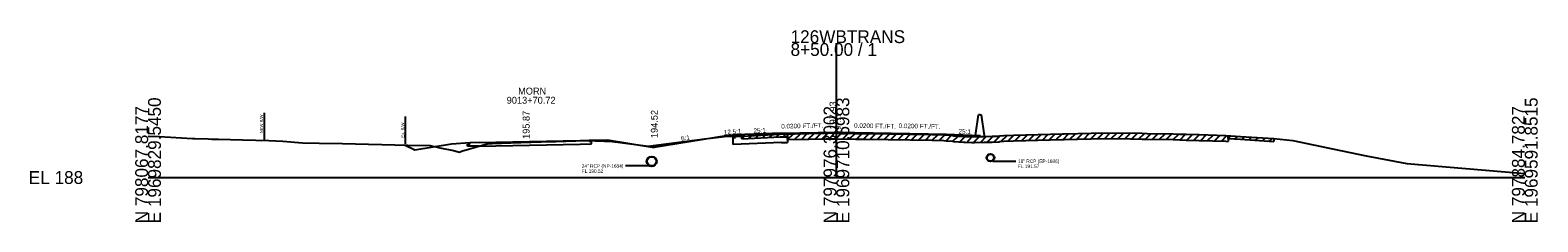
# Model space of a CAD drawing. Extents: x -6494 to 1970605, y -10 to 798140.
# Drawn here: x -25.7 to 302.8, y 990.3 to 1032.2 of the extents above; entities that cross this region are included whole.
import ezdxf

# ---------------------------------------------------------------- set-up
doc = ezdxf.new("R2010")
doc.units = 0
for name, color, linetype in [('RD_GPK_XS_Cell', 7, 'Continuous'), ('RD_XS_Base', 7, 'Continuous'), ('RD_XS_EarthShd', 7, 'Continuous'), ('RD_XS_ExGround', 7, 'Continuous'), ('RD_XS_ExPaveRet', 7, 'Continuous'), ('RD_XS_ExRW', 7, 'Continuous'), ('RD_XS_MedBWall', 7, 'Continuous'), ('RD_XS_Misc_Line', 7, 'Continuous'), ('RD_XS_NewRW', 7, 'Continuous'), ('RD_XS_Pave', 7, 'Continuous'), ('RD_XS_PaveOvlay', 7, 'Continuous'), ('RD_XS_PaveShd', 7, 'Continuous'), ('RD_XS_Pipe', 7, 'Continuous'), ('RD_XS_TieSlope', 7, 'Continuous'), ('RD_XS_TX_Elev_EX', 7, 'Continuous'), ('RD_XS_TX_Elev_PR', 7, 'Continuous'), ('RD_XS_TX_Misc', 7, 'Continuous'), ('RD_XS_TX_Profile', 7, 'Continuous'), ('RD_XS_TX_ShdSlope', 7, 'Continuous'), ('RD_XS_TX_Slope', 7, 'Continuous'), ('RD_XS_TX_Station', 7, 'Continuous')]:
    doc.layers.add(name, color=color, linetype=linetype)

msp = doc.modelspace()

# ---------------------------------------------------------------- linework, layer by layer
at = {"layer": 'RD_GPK_XS_Cell'}
for p, q in [((150, 1000), (150, 1029.35)), ((0, 1000), (150, 1000)), ((150, 1000), (300, 1000))]:
    msp.add_line(p, q, dxfattribs=at)
at = {"layer": 'RD_XS_Base'}
for p, q in [((127.5, 1008.71), (128, 1008.73)), ((127.5, 1007.23), (127.5, 1008.71)), ((128, 1008.73), (128, 1009.29)), ((69.64, 1007.29), (70.14, 1007.3)), ((69.64, 1006.81), (69.64, 1007.29)), ((72.14, 1006.86), (69.64, 1006.81)), ((70.14, 1007.3), (70.14, 1007.6)), ((94.14, 1007.31), (96.64, 1007.36)), ((96.14, 1007.83), (96.14, 1008.13)), ((96.64, 1007.84), (96.14, 1007.83)), ((96.64, 1007.36), (96.64, 1007.84)), ((138, 1007.65), (127.5, 1007.23)), ((138, 1007.65), (139.37, 1007.68))]:
    msp.add_line(p, q, dxfattribs=at)
at = {"layer": 'RD_XS_EarthShd'}
for p, q in [((128, 1009.29), (126, 1009.13)), ((70.14, 1007.6), (66.13, 1007.28)), ((96.14, 1008.13), (100.14, 1008.21))]:
    msp.add_line(p, q, dxfattribs=at)
at = {"layer": 'RD_XS_ExGround'}
msp.add_lwpolyline([(0, 1009), (2.52, 1008.93), (9.69, 1008.54), (10.19, 1008.53), (13.08, 1008.41), (13.87, 1008.39), (15.37, 1008.35), (20.59, 1008.25), (26.33, 1008.08), (29.35, 1007.9), (33.63, 1007.59), (37.29, 1007.49), (42.4, 1007.42), (56.62, 1007.07), (61.49, 1007.02), (63.6, 1006.51), (66.52, 1005.88), (67.89, 1005.52), (68.28, 1005.74), (73.89, 1007.36), (74.97, 1007.41), (79.08, 1007.56), (85.68, 1007.81), (88.82, 1007.88), (95.37, 1008.05), (99.44, 1007.97), (100.48, 1007.95), (102.33, 1007.71), (109, 1006.85), (121.29, 1008.46), (126.25, 1009.05), (127.43, 1009.06), (129.37, 1009.04), (137.76, 1009.5), (143.96, 1009.59), (147.74, 1009.68), (149.38, 1009.72), (150.2, 1009.71), (154.17, 1009.64), (156.42, 1009.62), (161.26, 1009.54), (170.76, 1009.37), (173.37, 1009.31), (173.9, 1009.29), (175.33, 1009.2), (175.61, 1009.1), (177.78, 1008.96), (178.08, 1008.94), (179.51, 1008.92), (180.09, 1008.92), (182.21, 1008.94), (183.91, 1009), (185.36, 1009.05), (185.6, 1009.13), (186.51, 1009.17), (188.58, 1009.26), (199.26, 1009.56), (199.59, 1009.57), (205.5, 1009.66), (211.52, 1009.78), (216.65, 1009.65), (217.74, 1009.63), (223.39, 1009.54), (224.8, 1009.49), (226.21, 1009.44), (229.05, 1009.36), (234.88, 1009.16), (238.06, 1008.97), (245.34, 1008.5), (248.04, 1008.22), (249.42, 1008.07), (258.46, 1006.16), (265.4, 1004.74), (274.3, 1003.04), (287.15, 1002), (300, 1000.88)], dxfattribs=at)
at = {"layer": 'RD_XS_ExPaveRet'}
for p, q in [((129.37, 1008.41), (129.37, 1009.04)), ((129.37, 1008.41), (137.76, 1008.87)), ((137.76, 1008.87), (139.37, 1008.9)), ((139.37, 1008.27), (139.37, 1009.52)), ((139.37, 1009.52), (139.37, 1008.9)), ((235.34, 1009.13), (235.34, 1007.88)), ((235.34, 1008.51), (235.34, 1009.13)), ((139.37, 1008.27), (143.96, 1008.34)), ((143.96, 1008.34), (147.74, 1008.43)), ((147.74, 1008.43), (149.38, 1008.47)), ((149.38, 1008.47), (150.2, 1008.46)), ((150.2, 1008.46), (154.17, 1008.39)), ((154.17, 1008.39), (156.42, 1008.37)), ((156.42, 1008.37), (161.26, 1008.29)), ((161.26, 1008.29), (170.76, 1008.12)), ((170.76, 1008.12), (173.37, 1008.06)), ((173.37, 1008.06), (173.9, 1008.04)), ((173.9, 1008.04), (175.33, 1007.95)), ((175.33, 1007.95), (175.61, 1007.85)), ((175.61, 1007.85), (177.78, 1007.71)), ((177.78, 1007.71), (178.08, 1007.69)), ((178.08, 1007.69), (179.51, 1007.67)), ((179.51, 1007.67), (180.09, 1007.67)), ((180.09, 1007.67), (182.21, 1007.69)), ((182.21, 1007.69), (183.91, 1007.75)), ((183.91, 1007.75), (185.36, 1007.8)), ((185.36, 1007.8), (185.6, 1007.88)), ((185.6, 1007.88), (186.51, 1007.92)), ((186.51, 1007.92), (188.58, 1008.01)), ((188.58, 1008.01), (199.26, 1008.31)), ((199.26, 1008.31), (199.59, 1008.32)), ((199.59, 1008.32), (205.5, 1008.41)), ((205.5, 1008.41), (211.52, 1008.53)), ((211.52, 1008.53), (216.65, 1008.4)), ((216.65, 1008.4), (217.74, 1008.38)), ((217.74, 1008.38), (223.39, 1008.29)), ((223.39, 1008.29), (224.8, 1008.24)), ((224.8, 1008.24), (226.21, 1008.19)), ((226.21, 1008.19), (229.05, 1008.11)), ((229.05, 1008.11), (234.88, 1007.91)), ((234.88, 1007.91), (235.34, 1007.88)), ((235.34, 1008.51), (238.06, 1008.34)), ((238.06, 1008.34), (245.34, 1007.87)), ((245.34, 1008.5), (245.34, 1007.87))]:
    msp.add_line(p, q, dxfattribs=at)
at = {"layer": 'RD_XS_ExRW'}
msp.add_line((56.06, 1013.33), (56.06, 1007.33), dxfattribs=at)
at = {"layer": 'RD_XS_MedBWall'}
for p, q in [((180.29, 1009.18), (180.96, 1013.66)), ((181.29, 1013.66), (180.96, 1013.66)), ((181.29, 1013.66), (181.63, 1013.66)), ((182.29, 1009.18), (181.63, 1013.66))]:
    msp.add_line(p, q, dxfattribs=at)
at = {"layer": 'RD_XS_Misc_Line'}
for p, q in [((129.37, 1008.41), (130.04, 1009.08)), ((130.87, 1008.5), (131.54, 1009.16)), ((132.37, 1008.58), (133.04, 1009.24)), ((133.87, 1008.66), (134.54, 1009.32)), ((135.37, 1008.74), (136.04, 1009.4)), ((136.87, 1008.82), (137.54, 1009.48)), ((138.37, 1008.88), (139.01, 1009.52)), ((139.37, 1008.27), (140.64, 1009.54)), ((140.87, 1008.29), (142.14, 1009.56)), ((142.37, 1008.32), (143.64, 1009.58)), ((143.87, 1008.34), (145.15, 1009.62)), ((145.37, 1008.37), (146.66, 1009.65)), ((146.88, 1008.41), (148.16, 1009.69)), ((148.38, 1008.45), (149.65, 1009.72)), ((149.88, 1008.46), (151.11, 1009.69)), ((151.38, 1008.44), (152.61, 1009.67)), ((152.88, 1008.41), (154.11, 1009.64)), ((154.38, 1008.39), (155.61, 1009.63)), ((155.88, 1008.37), (157.11, 1009.61)), ((157.38, 1008.35), (158.61, 1009.58)), ((158.88, 1008.33), (160.11, 1009.56)), ((160.38, 1008.31), (161.61, 1009.54)), ((161.88, 1008.28), (163.1, 1009.51)), ((163.38, 1008.25), (164.6, 1009.48)), ((164.88, 1008.23), (166.1, 1009.45)), ((166.38, 1008.2), (167.6, 1009.43)), ((167.88, 1008.17), (169.1, 1009.4)), ((169.38, 1008.14), (170.6, 1009.37)), ((170.88, 1008.12), (172.1, 1009.34)), ((172.38, 1008.08), (173.59, 1009.3)), ((173.88, 1008.04), (175.05, 1009.21)), ((175.38, 1007.93), (176.49, 1009.04)), ((176.88, 1007.77), (178.05, 1008.94)), ((178.38, 1007.68), (179.61, 1008.92)), ((179.88, 1007.67), (181.14, 1008.93)), ((181.38, 1007.68), (182.65, 1008.96)), ((182.88, 1007.71), (184.17, 1009.01)), ((184.38, 1007.77), (185.75, 1009.14)), ((185.88, 1007.9), (187.18, 1009.2)), ((187.38, 1007.96), (188.68, 1009.26)), ((188.88, 1008.02), (190.16, 1009.3)), ((190.38, 1008.06), (191.66, 1009.34)), ((191.88, 1008.1), (193.16, 1009.39)), ((193.38, 1008.14), (194.66, 1009.43)), ((194.88, 1008.18), (196.16, 1009.47)), ((196.38, 1008.23), (197.66, 1009.51)), ((197.88, 1008.27), (199.16, 1009.55)), ((199.38, 1008.31), (200.65, 1009.58)), ((200.88, 1008.34), (202.14, 1009.6)), ((202.38, 1008.36), (203.64, 1009.63)), ((203.88, 1008.38), (205.14, 1009.65)), ((205.38, 1008.4), (206.65, 1009.68)), ((206.88, 1008.43), (208.15, 1009.71)), ((208.38, 1008.47), (209.65, 1009.74)), ((209.88, 1008.5), (211.15, 1009.77)), ((211.38, 1008.53), (212.6, 1009.75)), ((212.88, 1008.5), (214.09, 1009.71)), ((214.38, 1008.46), (215.59, 1009.67)), ((215.88, 1008.42), (217.1, 1009.64)), ((217.38, 1008.38), (218.61, 1009.62)), ((218.88, 1008.36), (220.11, 1009.59)), ((220.38, 1008.34), (221.61, 1009.57)), ((221.88, 1008.32), (223.11, 1009.55)), ((223.38, 1008.29), (224.58, 1009.5)), ((224.88, 1008.24), (226.08, 1009.45)), ((226.38, 1008.19), (227.59, 1009.4)), ((227.88, 1008.14), (229.09, 1009.36)), ((229.38, 1008.1), (230.59, 1009.31)), ((230.88, 1008.05), (232.09, 1009.26)), ((232.38, 1008), (233.59, 1009.21)), ((233.88, 1007.95), (235.08, 1009.15)), ((235.34, 1008.51), (235.93, 1009.1)), ((236.84, 1008.42), (237.43, 1009)), ((238.34, 1008.32), (238.93, 1008.91)), ((239.84, 1008.23), (240.43, 1008.81)), ((241.34, 1008.13), (241.93, 1008.72)), ((242.84, 1008.03), (243.43, 1008.62)), ((244.34, 1007.94), (244.93, 1008.52))]:
    msp.add_line(p, q, dxfattribs=at)
at = {"layer": 'RD_XS_NewRW'}
msp.add_line((25.29, 1014.11), (25.29, 1008.11), dxfattribs=at)
at = {"layer": 'RD_XS_Pave'}
for p, q in [((138, 1009.69), (150, 1009.93)), ((150, 1009.93), (174, 1009.45)), ((72.14, 1007.64), (83.14, 1007.87)), ((72.14, 1006.86), (83.14, 1007.09)), ((83.14, 1007.87), (94.14, 1008.09)), ((83.14, 1007.09), (94.14, 1007.31))]:
    msp.add_line(p, q, dxfattribs=at)
at = {"layer": 'RD_XS_PaveOvlay'}
for p, q in [((139.37, 1009.52), (143.96, 1009.59)), ((139.37, 1009.52), (139.37, 1007.68)), ((143.96, 1009.59), (147.74, 1009.68)), ((147.74, 1009.68), (149.38, 1009.72)), ((149.38, 1009.72), (150.2, 1009.71)), ((150.2, 1009.71), (154.17, 1009.64)), ((154.17, 1009.64), (156.42, 1009.62)), ((156.42, 1009.62), (161.26, 1009.54)), ((161.26, 1009.54), (170.76, 1009.37)), ((170.76, 1009.37), (173.37, 1009.31)), ((173.37, 1009.31), (173.9, 1009.29)), ((173.9, 1009.29), (175.33, 1009.2)), ((175.33, 1009.2), (175.61, 1009.1)), ((175.61, 1009.1), (177.78, 1008.96)), ((177.78, 1008.96), (178.08, 1008.94)), ((178.08, 1008.94), (179.51, 1008.92)), ((179.51, 1008.92), (180.09, 1008.92)), ((180.09, 1008.92), (181.29, 1008.93))]:
    msp.add_line(p, q, dxfattribs=at)
at = {"layer": 'RD_XS_PaveShd'}
for p, q in [((138, 1009.69), (128, 1009.29)), ((174, 1009.45), (181.29, 1009.16)), ((181.29, 1008.93), (181.29, 1009.16)), ((72.14, 1007.64), (70.14, 1007.6)), ((94.14, 1008.09), (96.14, 1008.13))]:
    msp.add_line(p, q, dxfattribs=at)
at = {"layer": 'RD_XS_Pipe'}
for p, q in [((109.07, 1002.52), (104.07, 1002.52)), ((184.06, 1003.57), (189.06, 1003.57))]:
    msp.add_line(p, q, dxfattribs=at)
for centre, radius in [((109.74, 1003.52), 1.1), ((109.74, 1003.52), 1), ((183.56, 1004.32), 0.85), ((183.56, 1004.32), 0.75)]:
    msp.add_circle(centre, radius, dxfattribs=at)
at = {"layer": 'RD_XS_TieSlope'}
for p, q in [((126, 1009.13), (110.31, 1006.52)), ((58.13, 1005.95), (55.85, 1007.09)), ((66.13, 1007.28), (58.13, 1005.95)), ((100.14, 1008.21), (110.31, 1006.52)), ((110.31, 1006.52), (110.31, 1007.02))]:
    msp.add_line(p, q, dxfattribs=at)

# ---------------------------------------------------------------- texts
at = {"layer": 'RD_GPK_XS_Cell'}
for s, p in [('126WBTRANS', (140, 1029.35)), ('8+50.00 / 1', (140, 1026.55)), ('EL 188', (-26, 998.6))]:
    msp.add_text(s, height=2.8, dxfattribs=at).set_placement(p)
for s, p in [('N 798067.8177', (0, 990)), ('E 1969829.5450', (2.8, 990)), ('N 797976.3002', (150, 990)), ('E 1969710.6983', (152.8, 990)), ('N 797884.7827', (300, 990)), ('E 1969591.8515', (302.8, 990))]:
    msp.add_text(s, height=2.8, rotation=90, dxfattribs=at).set_placement(p)
at = {"layer": 'RD_XS_ExRW'}
msp.add_text('Ex. R/W ', height=0.65, rotation=90, dxfattribs=at).set_placement((55.81, 1008.72))
at = {"layer": 'RD_XS_NewRW'}
msp.add_text('NEW R/W ', height=0.65, rotation=90, dxfattribs=at).set_placement((25.02, 1009.67))
at = {"layer": 'RD_XS_Pipe'}
for s, p in [('24" RCP (NP-1684)', (94.51, 1002.14)), ('18" RCP (EP-1686)', (189.56, 1003.19)), ('FL 191.57', (189.56, 1002.07)), ('FL 190.52', (94.51, 1001.02))]:
    msp.add_text(s, height=0.75, dxfattribs=at).set_placement(p)
at = {"layer": 'RD_XS_TX_Elev_EX'}
msp.add_text('197.71', height=1, rotation=90, dxfattribs=at).set_placement((151, 1009.71))
at = {"layer": 'RD_XS_TX_Elev_PR'}
for s, p in [(' 197.93', (150, 1009.93)), (' 195.87', (83.14, 1007.87))]:
    msp.add_text(s, height=1.5, rotation=90, dxfattribs=at).set_placement(p)
at = {"layer": 'RD_XS_TX_Misc'}
msp.add_text('194.52', height=1.5, rotation=90, dxfattribs=at).set_placement((111.06, 1008.61))
at = {"layer": 'RD_XS_TX_Profile'}
for rotation, p in [(2.2906, (131.94, 1009.7)), (357.7094, (176.6, 1009.6))]:
    msp.add_text('25:1', height=1, rotation=rotation, dxfattribs=at).set_placement(p)
at = {"layer": 'RD_XS_TX_ShdSlope'}
msp.add_text('12.5:1', height=1, rotation=4.5739, dxfattribs=at).set_placement((125.5, 1009.35))
at = {"layer": 'RD_XS_TX_Slope'}
for s, rotation, p in [('0.0200 FT./FT.', 1.1458, (137.98, 1010.69)), ('6:1', 9.4623, (116.22, 1008.01)), ('0.0200 FT./FT.', 358.8542, (153.83, 1010.86)), ('0.0200 FT./FT.', 358.8542, (163.54, 1010.81))]:
    msp.add_text(s, height=1, rotation=rotation, dxfattribs=at).set_placement(p)
at = {"layer": 'RD_XS_TX_Station'}
for s, p in [('MORN', (80.63, 1018.12)), ('9013+70.72', (78.15, 1016.12))]:
    msp.add_text(s, height=1.5, dxfattribs=at).set_placement(p)

doc.saveas('drawing.dxf')
